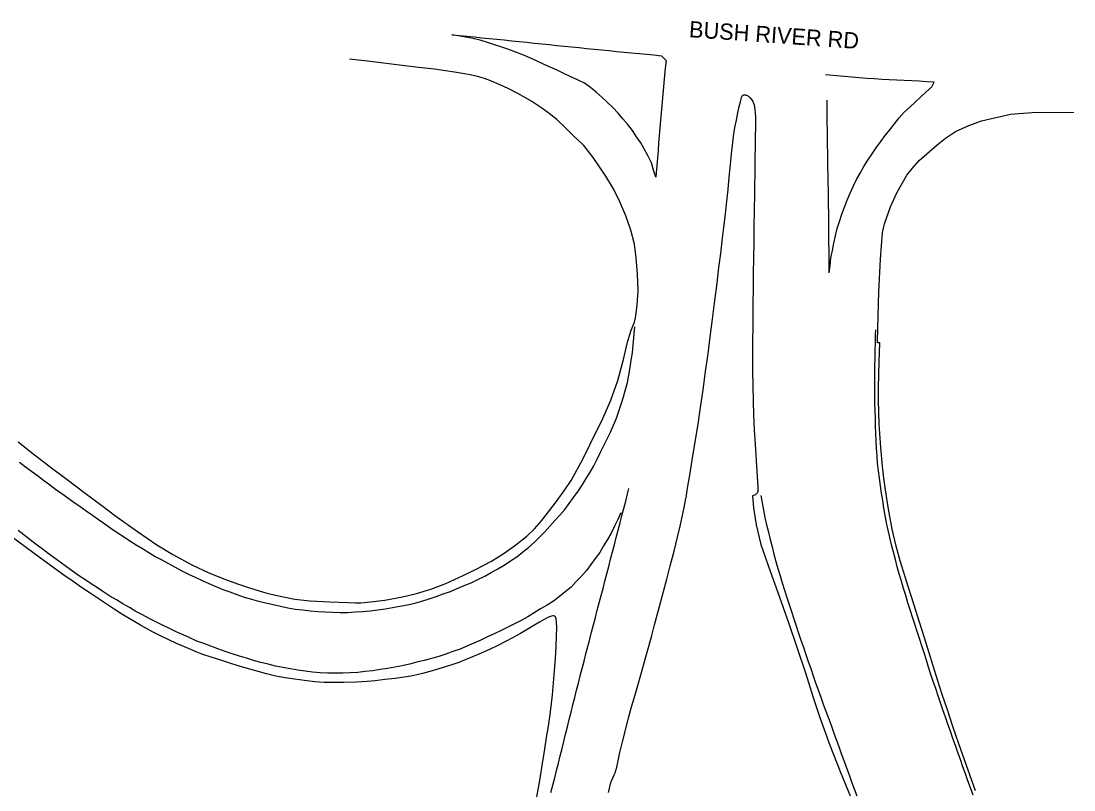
# Model space of a CAD drawing. Extents: x 1948091 to 1975253, y 787267 to 823306.
# Drawn here: x 1969109.2 to 1969459.1, y 799043.5 to 799299.1 of the extents above; entities that cross this region are included whole.
import ezdxf

# ---------------------------------------------------------------- set-up
doc = ezdxf.new("R2010")
doc.units = 0
for name, color, linetype in [('RD_EX_Pavement_Markings', 7, 'Continuous'), ('RD_EX_Road', 7, 'Continuous'), ('RD_TX_RoadID', 7, 'Continuous')]:
    doc.layers.add(name, color=color, linetype=linetype)

msp = doc.modelspace()

# ---------------------------------------------------------------- linework, layer by layer
at = {"layer": 'RD_EX_Pavement_Markings'}
for points in [[(1969252.4, 799294.53), (1969254.89, 799294.29), (1969257.38, 799294.04), (1969259.87, 799293.79), (1969262.35, 799293.54), (1969264.84, 799293.3), (1969267.33, 799293.04), (1969269.82, 799292.79), (1969272.3, 799292.54), (1969274.79, 799292.28), (1969277.28, 799292.03), (1969279.76, 799291.78), (1969282.25, 799291.52), (1969284.74, 799291.27), (1969287.23, 799291.01), (1969289.71, 799290.76), (1969292.2, 799290.51), (1969294.69, 799290.25), (1969297.17, 799290), (1969299.66, 799289.74), (1969302.15, 799289.5), (1969304.64, 799289.25), (1969307.12, 799289.01), (1969309.61, 799288.77), (1969312.1, 799288.53), (1969314.59, 799288.29), (1969317.08, 799288.05), (1969319.57, 799287.81), (1969322.05, 799287.56), (1969323.58, 799285.96), (1969323.33, 799283.47), (1969323.08, 799280.99), (1969322.83, 799278.5), (1969322.58, 799276.01), (1969322.36, 799273.52), (1969322.15, 799271.03), (1969321.94, 799268.55), (1969321.73, 799266.06), (1969321.52, 799263.57), (1969321.31, 799261.08), (1969321.11, 799258.59), (1969320.91, 799256.1), (1969320.71, 799253.61), (1969320.51, 799251.11), (1969320.31, 799248.62), (1969320.2, 799247.19)], [(1969320.2, 799247.19), (1969319.45, 799249.57), (1969318.69, 799251.96), (1969317.58, 799254.2), (1969316.46, 799256.43), (1969315.16, 799258.57), (1969313.78, 799260.65), (1969312.4, 799262.73), (1969310.84, 799264.68), (1969309.23, 799266.6), (1969307.63, 799268.51), (1969305.91, 799270.33), (1969304.1, 799272.06), (1969302.29, 799273.78), (1969300.4, 799275.41), (1969298.47, 799277), (1969296.43, 799278.45), (1969294.17, 799279.51), (1969291.91, 799280.58), (1969289.65, 799281.64), (1969287.39, 799282.71), (1969285.12, 799283.76), (1969282.85, 799284.8), (1969280.57, 799285.84), (1969278.3, 799286.88), (1969275.99, 799287.84), (1969273.65, 799288.72), (1969271.32, 799289.61), (1969268.95, 799290.43), (1969266.58, 799291.22), (1969264.21, 799292), (1969261.8, 799292.68), (1969259.39, 799293.33), (1969256.93, 799293.75), (1969254.46, 799294.18), (1969252.4, 799294.53)], [(1969377.82, 799215.38), (1969378.09, 799217.86), (1969378.39, 799220.34), (1969378.87, 799222.79), (1969379.35, 799225.25), (1969379.89, 799227.69), (1969380.5, 799230.11), (1969381.21, 799232.51), (1969381.96, 799234.89), (1969382.84, 799237.23), (1969383.75, 799239.56), (1969384.74, 799241.85), (1969385.76, 799244.13), (1969386.84, 799246.39), (1969388.08, 799248.56), (1969389.32, 799250.72), (1969390.68, 799252.82), (1969392.05, 799254.91), (1969393.46, 799256.97), (1969394.91, 799259), (1969396.39, 799261.02), (1969397.94, 799262.98), (1969399.49, 799264.94), (1969401.04, 799266.9), (1969402.71, 799268.75), (1969404.54, 799270.46), (1969406.36, 799272.17), (1969408.2, 799273.87), (1969410.03, 799275.57), (1969411.86, 799277.27), (1969412.73, 799278.81), (1969410.23, 799278.93), (1969407.73, 799279.05), (1969405.24, 799279.17), (1969402.74, 799279.3), (1969400.24, 799279.43), (1969397.75, 799279.56), (1969395.25, 799279.7), (1969392.75, 799279.83), (1969390.26, 799279.98), (1969387.77, 799280.2), (1969385.28, 799280.43), (1969382.79, 799280.65), (1969380.3, 799280.87), (1969377.81, 799281.1), (1969376.61, 799281.2)], [(1969377.82, 799215.38), (1969377.8, 799217.87), (1969377.78, 799220.37), (1969377.75, 799222.87), (1969377.73, 799225.37), (1969377.71, 799227.87), (1969377.69, 799230.37), (1969377.67, 799232.87), (1969377.65, 799235.37), (1969377.61, 799237.86), (1969377.57, 799240.36), (1969377.52, 799242.86), (1969377.48, 799245.36), (1969377.44, 799247.85), (1969377.39, 799250.35), (1969377.35, 799252.85), (1969377.31, 799255.35), (1969377.27, 799257.85), (1969377.23, 799260.35), (1969377.19, 799262.84), (1969377.15, 799265.34), (1969377.13, 799267.84), (1969377.11, 799270.34), (1969377.09, 799272.8)], [(1969108.67, 799152.46), (1969110.68, 799150.96), (1969112.68, 799149.47), (1969114.69, 799147.98), (1969116.7, 799146.49), (1969118.7, 799145), (1969120.73, 799143.54), (1969122.76, 799142.07), (1969124.79, 799140.61), (1969126.81, 799139.15), (1969128.84, 799137.69), (1969130.89, 799136.26), (1969132.94, 799134.82), (1969134.98, 799133.39), (1969137.03, 799131.95), (1969139.08, 799130.52), (1969141.16, 799129.14), (1969143.25, 799127.75), (1969145.33, 799126.37), (1969147.44, 799125.03), (1969149.57, 799123.72), (1969151.7, 799122.41), (1969153.85, 799121.14), (1969156.05, 799119.95), (1969158.24, 799118.75), (1969160.44, 799117.56), (1969162.64, 799116.38), (1969164.89, 799115.29), (1969167.14, 799114.19), (1969169.39, 799113.1), (1969171.68, 799112.11), (1969173.99, 799111.15), (1969176.3, 799110.19), (1969178.64, 799109.32), (1969180.99, 799108.45), (1969183.35, 799107.63), (1969185.76, 799106.97), (1969188.17, 799106.31), (1969190.59, 799105.69), (1969193.02, 799105.13), (1969195.46, 799104.56), (1969197.91, 799104.1), (1969200.37, 799103.65), (1969202.85, 799103.33), (1969205.33, 799103.02), (1969207.82, 799102.85), (1969210.32, 799102.72), (1969212.81, 799102.58), (1969215.31, 799102.51), (1969217.81, 799102.53), (1969220.3, 799102.67), (1969222.8, 799102.81), (1969225.28, 799103.07), (1969227.76, 799103.39), (1969230.23, 799103.76), (1969232.69, 799104.18), (1969235.16, 799104.59), (1969237.61, 799105.09), (1969240.05, 799105.61), (1969242.45, 799106.3), (1969244.85, 799107.01), (1969247.21, 799107.79), (1969249.56, 799108.66), (1969251.9, 799109.52), (1969254.21, 799110.46), (1969256.51, 799111.43), (1969258.81, 799112.41), (1969261.05, 799113.5), (1969263.3, 799114.59), (1969265.49, 799115.77), (1969267.68, 799116.98), (1969269.82, 799118.25), (1969271.89, 799119.64), (1969273.96, 799121.04), (1969275.92, 799122.58), (1969277.86, 799124.14), (1969279.72, 799125.8), (1969281.48, 799127.57), (1969283.24, 799129.33), (1969284.94, 799131.16), (1969286.59, 799133.03), (1969288.24, 799134.9), (1969289.89, 799136.77), (1969291.39, 799138.76), (1969292.87, 799140.77), (1969294.35, 799142.78), (1969295.7, 799144.87), (1969297, 799147), (1969298.31, 799149.13), (1969299.55, 799151.29), (1969300.68, 799153.51), (1969301.82, 799155.74), (1969302.95, 799157.96), (1969304.06, 799160.2), (1969305.07, 799162.48), (1969306.08, 799164.76), (1969307.09, 799167.05), (1969307.88, 799169.42), (1969308.66, 799171.79), (1969309.44, 799174.16), (1969310.08, 799176.58), (1969310.72, 799178.99), (1969311.25, 799181.43), (1969311.64, 799183.9), (1969312.03, 799186.37), (1969312.38, 799188.84), (1969312.6, 799191.33), (1969312.83, 799193.82), (1969313.06, 799196.31), (1969313.16, 799197.4)], [(1969425.61, 799041.82), (1969424.77, 799044.17), (1969423.92, 799046.52), (1969423.07, 799048.87), (1969422.24, 799051.23), (1969421.41, 799053.59), (1969420.57, 799055.94), (1969419.74, 799058.3), (1969418.91, 799060.66), (1969418.08, 799063.01), (1969417.24, 799065.37), (1969416.42, 799067.73), (1969415.61, 799070.1), (1969414.8, 799072.46), (1969413.99, 799074.83), (1969413.18, 799077.19), (1969412.38, 799079.56), (1969411.61, 799081.94), (1969410.85, 799084.32), (1969410.08, 799086.7), (1969409.31, 799089.08), (1969408.55, 799091.46), (1969407.78, 799093.84), (1969407.01, 799096.22), (1969406.25, 799098.6), (1969405.48, 799100.98), (1969404.72, 799103.36), (1969403.96, 799105.74), (1969403.23, 799108.13), (1969402.5, 799110.52), (1969401.77, 799112.91), (1969401.05, 799115.31), (1969400.42, 799117.72), (1969399.78, 799120.14), (1969399.14, 799122.56), (1969398.5, 799124.98), (1969397.96, 799127.41), (1969397.42, 799129.86), (1969396.89, 799132.3), (1969396.35, 799134.74), (1969395.96, 799137.21), (1969395.58, 799139.68), (1969395.2, 799142.15), (1969394.83, 799144.62), (1969394.51, 799147.1), (1969394.2, 799149.58), (1969393.89, 799152.06), (1969393.71, 799154.56), (1969393.55, 799157.05), (1969393.4, 799159.55), (1969393.31, 799162.05), (1969393.23, 799164.55), (1969393.14, 799167.04), (1969393.05, 799169.54), (1969392.97, 799172.04), (1969392.94, 799174.54), (1969392.95, 799177.04), (1969392.95, 799179.54), (1969392.96, 799182.04), (1969392.99, 799184.54), (1969393.05, 799187.04), (1969393.1, 799189.54), (1969393.16, 799192.04), (1969393.22, 799194.54), (1969393.26, 799196.4)], [(1969285.34, 799042.7), (1969285.98, 799045.11), (1969286.6, 799047.53), (1969287.2, 799049.96), (1969287.8, 799052.39), (1969288.4, 799054.82), (1969289, 799057.24), (1969289.59, 799059.67), (1969290.19, 799062.1), (1969290.81, 799064.52), (1969291.42, 799066.94), (1969292.03, 799069.37), (1969292.64, 799071.79), (1969293.25, 799074.21), (1969293.87, 799076.64), (1969294.48, 799079.06), (1969295.09, 799081.49), (1969295.7, 799083.91), (1969296.33, 799086.33), (1969296.96, 799088.75), (1969297.59, 799091.17), (1969298.22, 799093.59), (1969298.85, 799096), (1969299.48, 799098.42), (1969300.11, 799100.84), (1969300.74, 799103.26), (1969301.37, 799105.68), (1969302, 799108.1), (1969302.63, 799110.52), (1969303.26, 799112.93), (1969303.89, 799115.35), (1969304.52, 799117.77), (1969305.15, 799120.19), (1969305.78, 799122.61), (1969306.41, 799125.02), (1969307.04, 799127.44), (1969307.66, 799129.86), (1969308.29, 799132.28), (1969308.91, 799134.7), (1969309.54, 799137.12), (1969310.16, 799139.54), (1969310.79, 799141.96), (1969311.24, 799143.71)], [(1969355.11, 799141.43), (1969355.54, 799138.97), (1969355.98, 799136.51), (1969356.43, 799134.05), (1969357.01, 799131.62), (1969357.59, 799129.18), (1969358.17, 799126.75), (1969358.8, 799124.33), (1969359.45, 799121.92), (1969360.1, 799119.5), (1969360.75, 799117.09), (1969361.46, 799114.7), (1969362.21, 799112.31), (1969362.95, 799109.92), (1969363.7, 799107.54), (1969364.46, 799105.16), (1969365.24, 799102.78), (1969366.03, 799100.41), (1969366.81, 799098.03), (1969367.6, 799095.66), (1969368.4, 799093.29), (1969369.21, 799090.93), (1969370.03, 799088.57), (1969370.84, 799086.2), (1969371.66, 799083.84), (1969372.47, 799081.47), (1969373.28, 799079.11), (1969374.13, 799076.76), (1969374.99, 799074.41), (1969375.84, 799072.06), (1969376.7, 799069.71), (1969377.55, 799067.36), (1969378.41, 799065.01), (1969379.26, 799062.67), (1969380.12, 799060.32), (1969380.97, 799057.97), (1969381.82, 799055.62), (1969382.68, 799053.27), (1969383.53, 799050.92), (1969384.38, 799048.57), (1969385.24, 799046.22), (1969386.1, 799043.87), (1969386.98, 799041.53)], [(1969308.6, 799135.67), (1969307.55, 799133.4), (1969306.5, 799131.14), (1969305.37, 799128.91), (1969304.1, 799126.76), (1969302.82, 799124.61), (1969301.53, 799122.48), (1969300.05, 799120.47), (1969298.57, 799118.45), (1969297.09, 799116.44), (1969295.44, 799114.57), (1969293.74, 799112.75), (1969292.04, 799110.92), (1969290.1, 799109.34), (1969288.14, 799107.81), (1969286.15, 799106.31), (1969284.03, 799104.99), (1969281.91, 799103.67), (1969279.79, 799102.35), (1969277.63, 799101.1), (1969275.45, 799099.88), (1969273.23, 799098.76), (1969271, 799097.63), (1969268.77, 799096.5), (1969266.51, 799095.44), (1969264.25, 799094.39), (1969261.98, 799093.33), (1969259.7, 799092.32), (1969257.4, 799091.34), (1969255.11, 799090.36), (1969252.76, 799089.5), (1969250.4, 799088.69), (1969248.04, 799087.88), (1969245.63, 799087.22), (1969243.22, 799086.56), (1969240.8, 799085.95), (1969238.36, 799085.38), (1969235.93, 799084.82), (1969233.47, 799084.36), (1969231.01, 799083.93), (1969228.55, 799083.5), (1969226.09, 799083.08), (1969223.6, 799082.85), (1969221.11, 799082.61), (1969218.61, 799082.45), (1969216.12, 799082.38), (1969213.62, 799082.3), (1969211.12, 799082.38), (1969208.62, 799082.49), (1969206.13, 799082.69), (1969203.65, 799082.95), (1969201.17, 799083.28), (1969198.72, 799083.76), (1969196.26, 799084.23), (1969193.81, 799084.71), (1969191.38, 799085.31), (1969188.96, 799085.9), (1969186.53, 799086.52), (1969184.15, 799087.28), (1969181.77, 799088.04), (1969179.39, 799088.8), (1969177.01, 799089.57), (1969174.67, 799090.44), (1969172.32, 799091.3), (1969169.97, 799092.16), (1969167.63, 799093.02), (1969165.35, 799094.05), (1969163.07, 799095.07), (1969160.79, 799096.1), (1969158.51, 799097.13), (1969156.27, 799098.24), (1969154.04, 799099.38), (1969151.82, 799100.52), (1969149.6, 799101.67), (1969147.41, 799102.88), (1969145.25, 799104.14), (1969143.1, 799105.41), (1969140.94, 799106.67), (1969138.78, 799107.93), (1969136.69, 799109.3), (1969134.6, 799110.67), (1969132.51, 799112.04), (1969130.42, 799113.42), (1969128.33, 799114.79), (1969126.3, 799116.25), (1969124.28, 799117.71), (1969122.25, 799119.18), (1969120.23, 799120.65), (1969118.21, 799122.13), (1969116.22, 799123.64), (1969114.23, 799125.15), (1969112.24, 799126.67), (1969110.25, 799128.18), (1969108.26, 799129.7)]]:
    msp.add_lwpolyline(points, dxfattribs=at)
at = {"layer": 'RD_EX_Road'}
for points in [[(1969108.25, 799159.19), (1969113.1, 799155.39), (1969118.48, 799151.25), (1969124.5, 799146.7), (1969130.55, 799142.17), (1969136.02, 799138.08), (1969140.76, 799134.57), (1969147.96, 799129.39), (1969154.3, 799125.04), (1969159.64, 799121.76), (1969166.22, 799118.22), (1969171.43, 799115.79), (1969176.62, 799113.65), (1969181.19, 799112.01), (1969185.15, 799110.66), (1969190.95, 799108.92), (1969195.29, 799107.88), (1969200.18, 799106.96), (1969205.2, 799106.41), (1969211.77, 799105.99), (1969217.8, 799105.77), (1969220.26, 799105.7), (1969222.18, 799105.76), (1969225.36, 799106.03), (1969230.09, 799106.63), (1969236.01, 799107.72), (1969240.67, 799108.81), (1969245.42, 799110.27), (1969250.41, 799112.15), (1969256.15, 799114.75), (1969260.74, 799116.99), (1969265.54, 799119.59), (1969269.8, 799122.2), (1969273.71, 799124.99), (1969277.32, 799127.88), (1969279.82, 799130.31), (1969282.21, 799132.99), (1969284.56, 799135.96), (1969287.34, 799139.7), (1969289.93, 799143.25), (1969292.03, 799146.34), (1969295.91, 799153.51), (1969298.39, 799158.41), (1969302.54, 799166.96), (1969305.24, 799173.07), (1969307.56, 799179.66), (1969309.44, 799186.61), (1969310.8, 799192.38), (1969311.95, 799196.3), (1969312.86, 799198.49), (1969313.04, 799198.98), (1969313.39, 799200.43), (1969313.97, 799204.62), (1969314.27, 799209.39), (1969314.14, 799214.98), (1969313.69, 799220.4), (1969313.08, 799224.93), (1969311.92, 799229.53), (1969310.21, 799234.36), (1969308.22, 799238.98), (1969306.1, 799243.32), (1969303.59, 799247.56), (1969299.38, 799253.7), (1969296.22, 799257.77), (1969295.74, 799258.31), (1969292.98, 799260.87), (1969290.13, 799263.63), (1969287.23, 799266.34), (1969284.33, 799268.73), (1969282.34, 799270.16), (1969278.97, 799272.32), (1969274.53, 799274.85), (1969270.87, 799276.78), (1969268.12, 799278.04), (1969265.62, 799279.07), (1969263.25, 799279.94), (1969260.88, 799280.63), (1969258.48, 799281.16), (1969255.98, 799281.65), (1969253.32, 799282.11), (1969250.28, 799282.57), (1969246.64, 799283.05), (1969241.36, 799283.69), (1969234.16, 799284.52), (1969224.36, 799285.7), (1969218.43, 799286.42)], [(1969304.41, 799042.62), (1969305.28, 799046), (1969305.56, 799046.82), (1969305.98, 799047.8), (1969306.36, 799048.58), (1969306.68, 799049.26), (1969306.92, 799049.94), (1969307.21, 799051.09), (1969307.64, 799053.16), (1969308.26, 799056.02), (1969309.1, 799059.52), (1969310.08, 799063.42), (1969311.14, 799067.46), (1969312.15, 799071.17), (1969313.02, 799074.08), (1969314.03, 799077.45), (1969315.44, 799082.55), (1969316.87, 799087.79), (1969317.92, 799091.6), (1969318.82, 799094.85), (1969319.78, 799098.38), (1969320.77, 799102.06), (1969321.74, 799105.73), (1969322.74, 799109.52), (1969323.81, 799113.57), (1969324.96, 799117.98), (1969326.23, 799122.87), (1969327.39, 799127.5), (1969328.24, 799131.14), (1969328.91, 799134.28), (1969329.56, 799137.42), (1969330.07, 799139.85), (1969330.3, 799140.86), (1969330.35, 799141.03), (1969330.42, 799141.49), (1969330.51, 799142.29), (1969330.86, 799144.47), (1969331.48, 799148.17), (1969332.31, 799153.18), (1969333.3, 799159.27), (1969334.22, 799165.13), (1969335.04, 799170.65), (1969335.87, 799176.48), (1969336.72, 799182.62), (1969337.52, 799188.5), (1969338.27, 799194.1), (1969339.04, 799200.02), (1969339.81, 799206.22), (1969340.52, 799211.99), (1969341.16, 799217.19), (1969341.74, 799221.84), (1969342.27, 799226.03), (1969342.81, 799230.43), (1969343.34, 799235.04), (1969343.79, 799239.27), (1969344.18, 799243.1), (1969344.57, 799247.17), (1969344.97, 799251.43), (1969345.32, 799254.98), (1969345.62, 799257.72), (1969345.87, 799259.87), (1969346.1, 799261.58), (1969346.46, 799263.68), (1969346.95, 799266.19), (1969347.45, 799268.56), (1969347.92, 799270.64), (1969348.27, 799272.19), (1969348.51, 799273.17), (1969348.69, 799273.79), (1969348.77, 799273.98), (1969348.85, 799274.11), (1969348.93, 799274.23), (1969349.03, 799274.33), (1969349.13, 799274.42), (1969349.25, 799274.49), (1969349.39, 799274.54), (1969349.55, 799274.56), (1969349.74, 799274.57), (1969349.95, 799274.54), (1969350.17, 799274.49), (1969350.4, 799274.4), (1969350.64, 799274.29), (1969350.88, 799274.15), (1969351.12, 799273.98), (1969351.34, 799273.78), (1969351.55, 799273.55), (1969351.96, 799273), (1969352.37, 799272.32), (1969352.56, 799271.95), (1969352.71, 799271.59), (1969352.83, 799271.23), (1969352.97, 799270.52), (1969353.1, 799269.67), (1969353.24, 799268.63), (1969353.29, 799267.18), (1969353.26, 799264.95), (1969353.18, 799259.7), (1969353.08, 799251.34), (1969352.94, 799241.52), (1969352.87, 799236.18), (1969352.78, 799230.74), (1969352.7, 799225.43), (1969352.63, 799220.25), (1969352.55, 799215.18), (1969352.48, 799210.16), (1969352.42, 799205.12), (1969352.38, 799200.04), (1969352.34, 799190.17), (1969352.34, 799182.72), (1969352.4, 799177.68), (1969352.49, 799172.9), (1969352.62, 799168.04), (1969352.84, 799163.2), (1969353.14, 799158.32), (1969353.5, 799153), (1969353.87, 799147.54), (1969354.08, 799144.2), (1969354.11, 799143.47), (1969354.1, 799143.08), (1969354.05, 799142.73), (1969353.96, 799142.43), (1969353.83, 799142.17), (1969353.66, 799141.96), (1969353.47, 799141.78), (1969353.26, 799141.63), (1969353.02, 799141.51), (1969352.58, 799141.35), (1969352.29, 799141.26), (1969352.64, 799137.29), (1969353.49, 799131.67), (1969355.04, 799125.13), (1969358.23, 799116.22), (1969360.6, 799109.48), (1969364.35, 799098.88), (1969367.16, 799090.64), (1969369.89, 799082.45), (1969372.47, 799074.23), (1969374.74, 799067.63), (1969378.02, 799058.42), (1969381.42, 799049.66), (1969384.76, 799041.58)], [(1969426.46, 799043.2), (1969424.52, 799048.53), (1969422.76, 799053.52), (1969420.89, 799058.89), (1969418.92, 799064.66), (1969417.06, 799070.14), (1969415.35, 799075.23), (1969413.78, 799080.13), (1969410.91, 799089.46), (1969409.51, 799094.04), (1969407.84, 799099.3), (1969405.93, 799105.22), (1969404.13, 799110.85), (1969401.43, 799119.63), (1969400.08, 799124.51), (1969398.71, 799130.24), (1969397.46, 799136.84), (1969396.48, 799143.23), (1969395.91, 799147.19), (1969395.47, 799151.11), (1969394.92, 799157.38), (1969394.45, 799165.11), (1969394.16, 799173.17), (1969394.15, 799177.25), (1969394.38, 799185.86), (1969394.59, 799192.13), (1969393.8, 799192.15), (1969393.81, 799192.73), (1969394.31, 799209.12), (1969394.85, 799219.93), (1969395.49, 799228.8), (1969396.15, 799231.63), (1969398.2, 799237.39), (1969400.28, 799241.97), (1969403.63, 799247.81), (1969405.45, 799250.23), (1969407.69, 799252.68), (1969413.65, 799257.98), (1969416.45, 799260.12), (1969419.82, 799262.34), (1969424.19, 799264.42), (1969428.39, 799265.9), (1969438.01, 799268.09), (1969445.27, 799268.7), (1969459.13, 799268.84)], [(1969280.63, 799041.23), (1969281.58, 799046.69), (1969282.38, 799051.64), (1969283.16, 799056.39), (1969283.9, 799060.91), (1969284.51, 799064.7), (1969284.99, 799067.83), (1969285.41, 799071.27), (1969285.79, 799075.13), (1969286.15, 799079.1), (1969286.5, 799083.12), (1969286.8, 799087.24), (1969287.04, 799091.35), (1969287.18, 799094.79), (1969287.23, 799097.43), (1969287.19, 799099.28), (1969287.06, 799100.38), (1969286.97, 799100.75), (1969286.87, 799101.01), (1969286.75, 799101.17), (1969286.61, 799101.26), (1969286.47, 799101.33), (1969286.32, 799101.37), (1969286.16, 799101.38), (1969285.97, 799101.37), (1969285.5, 799101.29), (1969284.87, 799101.1), (1969284.06, 799100.74), (1969283.02, 799100.18), (1969281.53, 799099.31), (1969279.59, 799098.13), (1969277.45, 799096.85), (1969275.16, 799095.52), (1969272.76, 799094.18), (1969270.25, 799092.83), (1969267.64, 799091.5), (1969264.93, 799090.19), (1969262.12, 799088.94), (1969259.29, 799087.77), (1969256.8, 799086.74), (1969254.67, 799085.88), (1969252.67, 799085.16), (1969250.67, 799084.53), (1969248.11, 799083.77), (1969245.08, 799082.88), (1969242.61, 799082.2), (1969240.73, 799081.77), (1969238.76, 799081.38), (1969236.51, 799081), (1969233.58, 799080.6), (1969230.07, 799080.19), (1969226.96, 799079.83), (1969224.22, 799079.52), (1969220.72, 799079.31), (1969216.48, 799079.21), (1969212.86, 799079.19), (1969209.95, 799079.26), (1969206.83, 799079.5), (1969203.42, 799079.87), (1969200.13, 799080.3), (1969197.01, 799080.78), (1969193.94, 799081.37), (1969190.83, 799082.1), (1969187.25, 799083.07), (1969183.22, 799084.27), (1969179.29, 799085.46), (1969175.61, 799086.61), (1969172.38, 799087.65), (1969169.65, 799088.58), (1969167.46, 799089.4), (1969165.68, 799090.15), (1969163.53, 799091.09), (1969160.94, 799092.24), (1969158.29, 799093.45), (1969155.57, 799094.73), (1969152.44, 799096.34), (1969148.93, 799098.24), (1969145.67, 799100.14), (1969142.75, 799101.97), (1969140.16, 799103.65), (1969137.8, 799105.21), (1969135.17, 799106.96), (1969132.22, 799108.91), (1969129.33, 799110.86), (1969126.5, 799112.78), (1969123.47, 799114.91), (1969120.22, 799117.23), (1969116.94, 799119.62), (1969113.63, 799122.07), (1969110.13, 799124.68), (1969106.42, 799127.47)]]:
    msp.add_lwpolyline(points, dxfattribs=at)

# ---------------------------------------------------------------- texts
at = {"layer": 'RD_TX_RoadID'}
msp.add_text('BUSH RIVER RD', height=5.4, rotation=356.0096, dxfattribs=at).set_placement((1969331.08, 799293.74))

doc.saveas('drawing.dxf')
